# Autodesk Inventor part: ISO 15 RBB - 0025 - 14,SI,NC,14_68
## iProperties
Created: 2011-01
Part Number: ISO 15 RBB - 0025 - 14,SI,NC,14_68
Document SubType Name: Modeling
Designer: eric
Density: 1 g/cm^3
Mass: 8.98431 g
Surface Area: 50.3042 cm^2
Volume: 8.98431 cm^3
Author: eric
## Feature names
1. Base1
